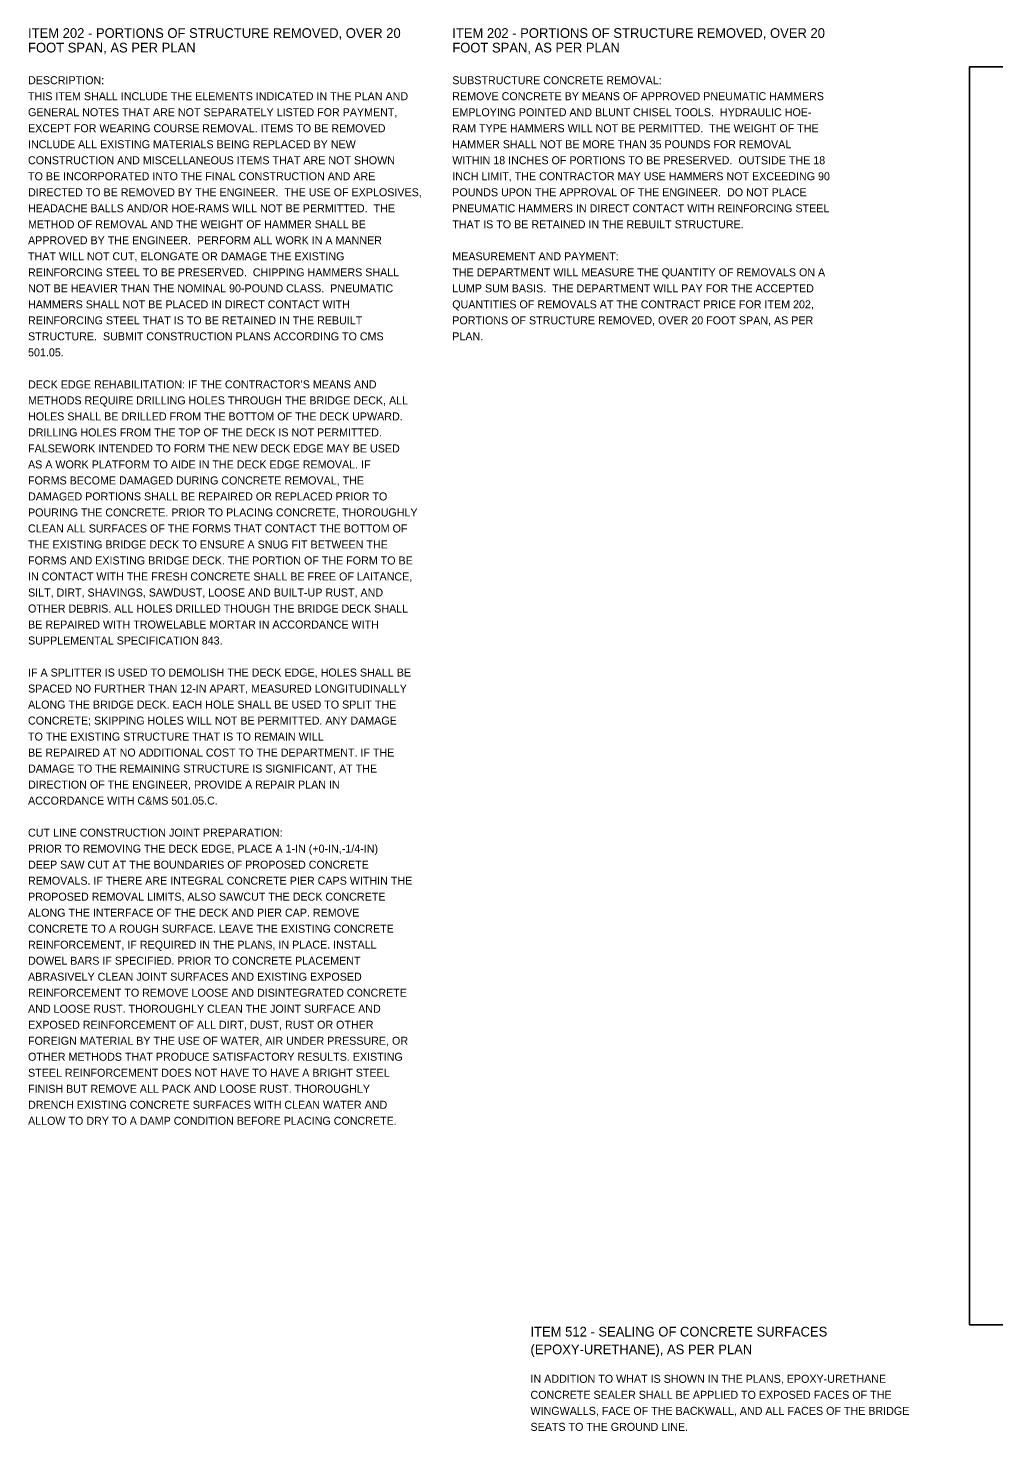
# Model space of a CAD drawing. Extents: x -16.5 to 61.9, y -20 to 22.7.
# Drawn here: x -16.47 to 0.43, y -1.86 to 22.68 of the extents above; entities that cross this region are included whole.
import ezdxf

# ---------------------------------------------------------------- set-up
doc = ezdxf.new("R2010")
doc.units = 0
for name, color, linetype in [('SH_Cut_Line', 7, 'Continuous'), ('SH_Data', 7, 'Continuous'), ('SH_Text', 7, 'Continuous')]:
    doc.layers.add(name, color=color, linetype=linetype)

msp = doc.modelspace()

# ---------------------------------------------------------------- linework, layer by layer
at = {"layer": 'SH_Cut_Line'}
msp.add_lwpolyline([(0, 0), (34, 0), (34, 22), (0, 22)], close=True, dxfattribs=at)
at = {"layer": 'SH_Data'}
msp.add_line((0, 0), (0, 0), dxfattribs=at)

# ---------------------------------------------------------------- texts
at = {"layer": 'SH_Text'}
for s, height, p in [('ITEM 202 - PORTIONS OF STRUCTURE REMOVED, OVER 20', 0.17, (-16.466, 22.507)), ('ITEM 202 - PORTIONS OF STRUCTURE REMOVED, OVER 20', 0.17, (-9.046, 22.507)), ('FOOT SPAN, AS PER PLAN', 0.17, (-16.466, 22.252)), ('FOOT SPAN, AS PER PLAN', 0.17, (-9.046, 22.252)), ('DESCRIPTION:', 0.14, (-16.466, 21.697)), ('SUBSTRUCTURE CONCRETE REMOVAL:', 0.14, (-9.046, 21.697)), ('THIS ITEM SHALL INCLUDE THE ELEMENTS INDICATED IN THE PLAN AND ', 0.14, (-16.466, 21.417)), ('REMOVE CONCRETE BY MEANS OF APPROVED PNEUMATIC HAMMERS ', 0.14, (-9.046, 21.417)), ('GENERAL NOTES THAT ARE NOT SEPARATELY LISTED FOR PAYMENT, ', 0.14, (-16.466, 21.137)), ('EMPLOYING POINTED AND BLUNT CHISEL TOOLS.  HYDRAULIC HOE-', 0.14, (-9.046, 21.137)), ('EXCEPT FOR WEARING COURSE REMOVAL. ITEMS TO BE REMOVED ', 0.14, (-16.466, 20.857)), ('RAM TYPE HAMMERS WILL NOT BE PERMITTED.  THE WEIGHT OF THE ', 0.14, (-9.046, 20.857)), ('INCLUDE ALL EXISTING MATERIALS BEING REPLACED BY NEW ', 0.14, (-16.466, 20.577)), ('HAMMER SHALL NOT BE MORE THAN 35 POUNDS FOR REMOVAL ', 0.14, (-9.046, 20.577)), ('CONSTRUCTION AND MISCELLANEOUS ITEMS THAT ARE NOT SHOWN ', 0.14, (-16.466, 20.297)), ('WITHIN 18 INCHES OF PORTIONS TO BE PRESERVED.  OUTSIDE THE 18 ', 0.14, (-9.046, 20.297)), ('TO BE INCORPORATED INTO THE FINAL CONSTRUCTION AND ARE ', 0.14, (-16.466, 20.017)), ('INCH LIMIT, THE CONTRACTOR MAY USE HAMMERS NOT EXCEEDING 90 ', 0.14, (-9.046, 20.017)), ('DIRECTED TO BE REMOVED BY THE ENGINEER.  THE USE OF EXPLOSIVES, ', 0.14, (-16.466, 19.737)), ('POUNDS UPON THE APPROVAL OF THE ENGINEER.  DO NOT PLACE ', 0.14, (-9.046, 19.737)), ('HEADACHE BALLS AND/OR HOE-RAMS WILL NOT BE PERMITTED.  THE ', 0.14, (-16.466, 19.457)), ('PNEUMATIC HAMMERS IN DIRECT CONTACT WITH REINFORCING STEEL ', 0.14, (-9.046, 19.457)), ('METHOD OF REMOVAL AND THE WEIGHT OF HAMMER SHALL BE ', 0.14, (-16.466, 19.177)), ('THAT IS TO BE RETAINED IN THE REBUILT STRUCTURE.', 0.14, (-9.046, 19.177)), ('APPROVED BY THE ENGINEER.  PERFORM ALL WORK IN A MANNER ', 0.14, (-16.466, 18.897)), ('THAT WILL NOT CUT, ELONGATE OR DAMAGE THE EXISTING ', 0.14, (-16.466, 18.617)), ('MEASUREMENT AND PAYMENT:', 0.14, (-9.046, 18.617)), ('REINFORCING STEEL TO BE PRESERVED.  CHIPPING HAMMERS SHALL ', 0.14, (-16.466, 18.337)), ('THE DEPARTMENT WILL MEASURE THE QUANTITY OF REMOVALS ON A ', 0.14, (-9.046, 18.337)), ('NOT BE HEAVIER THAN THE NOMINAL 90-POUND CLASS.  PNEUMATIC ', 0.14, (-16.466, 18.057)), ('LUMP SUM BASIS.  THE DEPARTMENT WILL PAY FOR THE ACCEPTED ', 0.14, (-9.046, 18.057)), ('HAMMERS SHALL NOT BE PLACED IN DIRECT CONTACT WITH ', 0.14, (-16.466, 17.777)), ('QUANTITIES OF REMOVALS AT THE CONTRACT PRICE FOR ITEM 202, ', 0.14, (-9.046, 17.777)), ('REINFORCING STEEL THAT IS TO BE RETAINED IN THE REBUILT ', 0.14, (-16.466, 17.497)), ('PORTIONS OF STRUCTURE REMOVED, OVER 20 FOOT SPAN, AS PER ', 0.14, (-9.046, 17.497)), ('STRUCTURE.  SUBMIT CONSTRUCTION PLANS ACCORDING TO CMS ', 0.14, (-16.466, 17.217)), ('PLAN.', 0.14, (-9.046, 17.217)), ('501.05.', 0.14, (-16.466, 16.937)), ('DECK EDGE REHABILITATION: IF THE CONTRACTOR’S MEANS AND ', 0.14, (-16.466, 16.377)), ('METHODS REQUIRE DRILLING HOLES THROUGH THE BRIDGE DECK, ALL ', 0.14, (-16.466, 16.097)), ('HOLES SHALL BE DRILLED FROM THE BOTTOM OF THE DECK UPWARD. ', 0.14, (-16.466, 15.817)), ('DRILLING HOLES FROM THE TOP OF THE DECK IS NOT PERMITTED. ', 0.14, (-16.466, 15.537)), ('FALSEWORK INTENDED TO FORM THE NEW DECK EDGE MAY BE USED ', 0.14, (-16.466, 15.257)), ('AS A WORK PLATFORM TO AIDE IN THE DECK EDGE REMOVAL. IF ', 0.14, (-16.466, 14.977)), ('FORMS BECOME DAMAGED DURING CONCRETE REMOVAL, THE ', 0.14, (-16.466, 14.697)), ('DAMAGED PORTIONS SHALL BE REPAIRED OR REPLACED PRIOR TO ', 0.14, (-16.466, 14.417)), ('POURING THE CONCRETE. PRIOR TO PLACING CONCRETE, THOROUGHLY ', 0.14, (-16.466, 14.137)), ('CLEAN ALL SURFACES OF THE FORMS THAT CONTACT THE BOTTOM OF ', 0.14, (-16.466, 13.857)), ('THE EXISTING BRIDGE DECK TO ENSURE A SNUG FIT BETWEEN THE ', 0.14, (-16.466, 13.577)), ('FORMS AND EXISTING BRIDGE DECK. THE PORTION OF THE FORM TO BE ', 0.14, (-16.466, 13.297)), ('IN CONTACT WITH THE FRESH CONCRETE SHALL BE FREE OF LAITANCE, ', 0.14, (-16.466, 13.017)), ('SILT, DIRT, SHAVINGS, SAWDUST, LOOSE AND BUILT-UP RUST, AND ', 0.14, (-16.466, 12.737)), ('OTHER DEBRIS. ALL HOLES DRILLED THOUGH THE BRIDGE DECK SHALL ', 0.14, (-16.466, 12.457)), ('BE REPAIRED WITH TROWELABLE MORTAR IN ACCORDANCE WITH ', 0.14, (-16.466, 12.177)), ('SUPPLEMENTAL SPECIFICATION 843.', 0.14, (-16.466, 11.897)), ('IF A SPLITTER IS USED TO DEMOLISH THE DECK EDGE, HOLES SHALL BE ', 0.14, (-16.466, 11.337)), ('SPACED NO FURTHER THAN 12-IN APART, MEASURED LONGITUDINALLY ', 0.14, (-16.466, 11.057)), ('ALONG THE BRIDGE DECK. EACH HOLE SHALL BE USED TO SPLIT THE ', 0.14, (-16.466, 10.777)), ('CONCRETE; SKIPPING HOLES WILL NOT BE PERMITTED. ANY DAMAGE ', 0.14, (-16.466, 10.497)), ('TO THE EXISTING STRUCTURE THAT IS TO REMAIN WILL ', 0.14, (-16.466, 10.217)), ('BE REPAIRED AT NO ADDITIONAL COST TO THE DEPARTMENT. IF THE ', 0.14, (-16.466, 9.937)), ('DAMAGE TO THE REMAINING STRUCTURE IS SIGNIFICANT, AT THE ', 0.14, (-16.466, 9.657)), ('DIRECTION OF THE ENGINEER, PROVIDE A REPAIR PLAN IN ', 0.14, (-16.466, 9.377)), ('ACCORDANCE WITH C&MS 501.05.C.', 0.14, (-16.466, 9.097)), ('CUT LINE CONSTRUCTION JOINT PREPARATION: ', 0.14, (-16.466, 8.537)), ('PRIOR TO REMOVING THE DECK EDGE, PLACE A 1-IN (+0-IN,-1/4-IN) ', 0.14, (-16.466, 8.257)), ('DEEP SAW CUT AT THE BOUNDARIES OF PROPOSED CONCRETE ', 0.14, (-16.466, 7.977)), ('REMOVALS. IF THERE ARE INTEGRAL CONCRETE PIER CAPS WITHIN THE ', 0.14, (-16.466, 7.697)), ('PROPOSED REMOVAL LIMITS, ALSO SAWCUT THE DECK CONCRETE ', 0.14, (-16.466, 7.417)), ('ALONG THE INTERFACE OF THE DECK AND PIER CAP. REMOVE ', 0.14, (-16.466, 7.137)), ('CONCRETE TO A ROUGH SURFACE. LEAVE THE EXISTING CONCRETE ', 0.14, (-16.466, 6.857)), ('REINFORCEMENT, IF REQUIRED IN THE PLANS, IN PLACE. INSTALL ', 0.14, (-16.466, 6.577)), ('DOWEL BARS IF SPECIFIED. PRIOR TO CONCRETE PLACEMENT ', 0.14, (-16.466, 6.297)), ('ABRASIVELY CLEAN JOINT SURFACES AND EXISTING EXPOSED ', 0.14, (-16.466, 6.017)), ('REINFORCEMENT TO REMOVE LOOSE AND DISINTEGRATED CONCRETE ', 0.14, (-16.466, 5.737)), ('AND LOOSE RUST. THOROUGHLY CLEAN THE JOINT SURFACE AND ', 0.14, (-16.466, 5.457)), ('EXPOSED REINFORCEMENT OF ALL DIRT, DUST, RUST OR OTHER ', 0.14, (-16.466, 5.177)), ('FOREIGN MATERIAL BY THE USE OF WATER, AIR UNDER PRESSURE, OR ', 0.14, (-16.466, 4.897)), ('OTHER METHODS THAT PRODUCE SATISFACTORY RESULTS. EXISTING ', 0.14, (-16.466, 4.617)), ('STEEL REINFORCEMENT DOES NOT HAVE TO HAVE A BRIGHT STEEL ', 0.14, (-16.466, 4.337)), ('FINISH BUT REMOVE ALL PACK AND LOOSE RUST. THOROUGHLY ', 0.14, (-16.466, 4.057)), ('DRENCH EXISTING CONCRETE SURFACES WITH CLEAN WATER AND ', 0.14, (-16.466, 3.777)), ('ALLOW TO DRY TO A DAMP CONDITION BEFORE PLACING CONCRETE. ', 0.14, (-16.466, 3.497)), ('ITEM 512 - SEALING OF CONCRETE SURFACES', 0.17, (-7.678, -0.206)), ('(EPOXY-URETHANE), AS PER PLAN', 0.17, (-7.678, -0.516)), ('IN ADDITION TO WHAT IS SHOWN IN THE PLANS, EPOXY-URETHANE ', 0.14, (-7.678, -1.016)), ('CONCRETE SEALER SHALL BE APPLIED TO EXPOSED FACES OF THE ', 0.14, (-7.678, -1.296)), ('WINGWALLS, FACE OF THE BACKWALL, AND ALL FACES OF THE BRIDGE ', 0.14, (-7.678, -1.576)), ('SEATS TO THE GROUND LINE. ', 0.14, (-7.678, -1.856))]:
    msp.add_text(s, height=height, dxfattribs=at).set_placement(p)

doc.saveas('drawing.dxf')
